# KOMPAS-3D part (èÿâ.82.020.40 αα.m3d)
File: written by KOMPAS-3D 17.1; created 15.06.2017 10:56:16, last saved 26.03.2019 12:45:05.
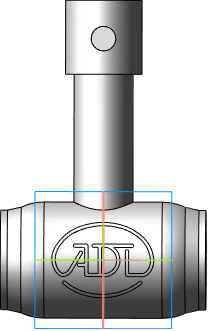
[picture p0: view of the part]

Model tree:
1. Операция без истории:2  (labels: Сталь 20  ГОСТ 1050-88)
